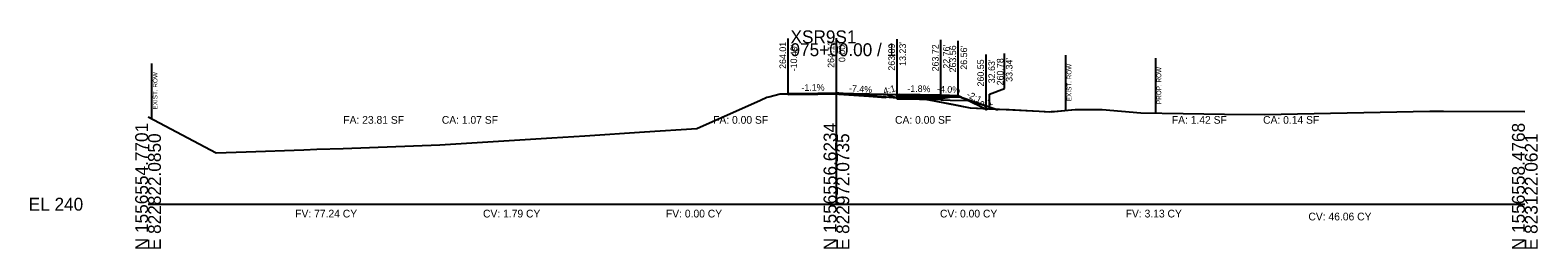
# Model space of a CAD drawing. Extents: x -26 to 823017, y -16 to 1558356.
# Drawn here: x 1974.3 to 2302.8, y 5990.3 to 6037.8 of the extents above; entities that cross this region are included whole.
import ezdxf

# ---------------------------------------------------------------- set-up
doc = ezdxf.new("R2010")
doc.units = 0
for name, color, linetype in [('ASPHALT_19MM1', 7, 'Continuous'), ('CONST_DCH', 7, 'Continuous'), ('CONST_LV3', 7, 'Continuous'), ('Draft_XS_Grid', 7, 'Continuous'), ('DTM_CORRIDOR', 7, 'Continuous'), ('DTM_P_FINISHED_GRADE2', 7, 'Continuous'), ('DTM_X_GROUND', 7, 'Continuous'), ('SLOPE_STAKES_FILL', 7, 'Continuous'), ('X_TRANS_EOP', 7, 'Continuous'), ('XS_CELL', 7, 'Continuous'), ('XS_P_ASPHALT', 7, 'Continuous'), ('XS_P_DR_GRAVEL', 7, 'Continuous'), ('XS_P_GROUND', 7, 'Continuous'), ('XS_P_NULL_POINT', 7, 'Continuous'), ('XS_P_ROW', 7, 'Continuous'), ('XS_P_SHOULDER', 7, 'Continuous'), ('XS_P_SUBGRADE_GRANULAR', 7, 'Continuous'), ('XS_P_SUBGRADE_LEVELING', 7, 'Continuous'), ('XS_P_SUBGRADE_MILLING', 7, 'Continuous'), ('XS_P_SUBGRADE_UNDERCUT', 7, 'Continuous'), ('XS_P_TX_CLEARZONE', 7, 'Continuous'), ('XS_P_TX_FS_BS', 7, 'Continuous'), ('XS_SHEET_EW_TX_AREA', 7, 'Continuous'), ('XS_SHEET_EW_TX_VOLUME', 7, 'Continuous'), ('XS_X_ROW', 7, 'Continuous')]:
    doc.layers.add(name, color=color, linetype=linetype)

msp = doc.modelspace()

# ---------------------------------------------------------------- linework, layer by layer
at = {"layer": 'ASPHALT_19MM1'}
msp.add_lwpolyline([(2163.23, 6023.72), (2163.23, 6023.51), (2172.76, 6023.34), (2172.76, 6023.55), (2163.23, 6023.72)], dxfattribs=at)
at = {"layer": 'CONST_LV3'}
for points in [[(2000, 6019.04), (2014.82, 6011.15), (2021.41, 6011.39), (2033.95, 6011.84), (2036.76, 6011.94), (2042.5, 6012.14), (2063.56, 6012.92), (2088.01, 6014.41), (2095.16, 6014.88), (2108.14, 6015.72), (2119.6, 6016.47), (2133.42, 6022.63), (2134.82, 6023.26), (2135.28, 6023.37), (2137.74, 6023.99), (2139.51, 6024.01), (2139.51, 6024.01)], [(2150, 6024.12), (2164, 6023.84)], [(2160.76, 6023.33), (2160.76, 6023.33), (2163.2, 6023.14), (2163.2, 6023.14), (2163.2, 6023.14), (2163.2, 6023.14), (2163.2, 6023.14), (2163.2, 6023.14), (2163.23, 6023.14), (2163.48, 6023.13), (2172.76, 6022.97), (2176.07, 6023.49), (2176.56, 6023.56), (2177.39, 6023.15), (2185.06, 6020.55), (2185.12, 6020.57), (2185.42, 6020.67), (2185.45, 6020.68), (2185.55, 6020.67), (2187.62, 6020.57), (2194.18, 6020.23), (2196.34, 6020.12), (2196.78, 6020.13), (2197.32, 6020.15), (2201.99, 6020.6), (2202.01, 6020.6), (2203.42, 6020.59), (2203.8, 6020.59), (2203.91, 6020.59), (2204.23, 6020.59), (2205.44, 6020.59), (2205.51, 6020.59), (2207.9, 6020.6), (2216.3, 6019.84), (2225.55, 6019.71), (2234.55, 6019.59), (2243.31, 6019.48), (2279.32, 6020.24), (2282.28, 6020.24), (2300, 6020.14)], [(2162.76, 6023.89), (2162.76, 6023.89), (2164, 6023.84)]]:
    msp.add_lwpolyline(points, dxfattribs=at)
at = {"layer": 'DTM_P_FINISHED_GRADE2'}
msp.add_lwpolyline([(2139.51, 6024.01), (2150, 6024.12), (2160.76, 6023.93)], dxfattribs=at)
at = {"layer": 'DTM_X_GROUND'}
for points in [[(2000, 6019.04), (2014.82, 6011.15), (2021.41, 6011.39), (2033.95, 6011.84), (2036.76, 6011.94), (2042.5, 6012.14), (2063.56, 6012.92), (2088.01, 6014.41), (2095.16, 6014.88), (2108.14, 6015.72), (2119.6, 6016.47), (2133.42, 6022.63), (2134.82, 6023.26), (2135.28, 6023.37), (2137.74, 6023.99), (2145.94, 6024.08), (2150.52, 6024.13), (2157.03, 6024.01), (2163.23, 6023.89), (2164.44, 6023.59), (2164.57, 6023.58), (2164.58, 6023.58), (2165.92, 6023.55), (2168.57, 6023.01), (2170.49, 6022.66), (2171.28, 6022.48), (2179.17, 6020.98), (2185.55, 6020.65), (2194.18, 6020.21), (2196.78, 6020.1), (2201.99, 6020.6), (2203.42, 6020.59), (2207.9, 6020.6), (2216.3, 6019.84), (2225.55, 6019.71), (2234.55, 6019.59), (2243.31, 6019.48), (2279.32, 6020.24), (2282.28, 6020.24), (2300, 6020.14)], [(2000, 6019.04), (2014.82, 6011.15), (2021.41, 6011.39), (2033.95, 6011.84), (2036.76, 6011.94), (2042.5, 6012.14), (2063.56, 6012.92), (2088.01, 6014.41), (2095.16, 6014.88), (2108.14, 6015.72), (2119.6, 6016.47), (2133.42, 6022.63), (2134.82, 6023.26), (2135.28, 6023.37), (2137.74, 6023.99), (2145.94, 6024.08), (2150.52, 6024.13), (2157.03, 6023.62), (2163.2, 6023.14), (2163.2, 6023.14), (2163.2, 6023.14), (2163.2, 6023.14), (2163.2, 6023.14), (2163.2, 6023.14), (2163.23, 6023.14), (2163.48, 6023.13), (2172.76, 6022.97), (2176.07, 6023.49), (2176.56, 6023.56), (2177.39, 6023.15), (2185.06, 6020.55), (2185.12, 6020.57), (2185.42, 6020.67), (2185.45, 6020.68), (2185.55, 6020.67), (2187.62, 6020.57), (2194.18, 6020.23), (2196.34, 6020.12), (2196.78, 6020.13), (2197.32, 6020.15), (2201.99, 6020.6), (2202.01, 6020.6), (2203.42, 6020.59), (2203.8, 6020.59), (2203.91, 6020.59), (2204.23, 6020.59), (2205.44, 6020.59), (2205.51, 6020.59), (2207.9, 6020.6), (2216.3, 6019.84), (2225.55, 6019.71), (2234.55, 6019.59), (2243.31, 6019.48), (2279.32, 6020.24), (2282.28, 6020.24), (2300, 6020.14)], [(2000, 6019.04), (2014.82, 6011.15), (2021.41, 6011.39), (2033.95, 6011.84), (2036.76, 6011.94), (2042.5, 6012.14), (2063.56, 6012.92), (2088.01, 6014.41), (2095.16, 6014.88), (2108.14, 6015.72), (2119.6, 6016.47), (2133.42, 6022.63), (2134.82, 6023.26), (2135.28, 6023.37), (2137.74, 6023.99), (2139.51, 6024.01), (2139.51, 6024.01), (2150, 6024.12), (2150, 6024.12), (2150, 6024.12), (2150, 6024.12), (2150, 6024.12), (2150, 6024.12), (2150, 6024.12), (2150, 6024.12), (2160.76, 6023.93), (2160.76, 6023.93), (2160.76, 6023.93), (2163.2, 6023.14), (2163.2, 6023.14), (2163.2, 6023.14), (2163.2, 6023.14), (2163.2, 6023.14), (2163.2, 6023.14), (2163.23, 6023.14), (2163.48, 6023.13), (2172.76, 6022.97), (2176.07, 6023.49), (2176.56, 6023.56), (2177.39, 6023.15), (2185.06, 6020.55), (2185.12, 6020.57), (2185.42, 6020.67), (2185.45, 6020.68), (2185.55, 6020.67), (2187.62, 6020.57), (2194.18, 6020.23), (2196.34, 6020.12), (2196.78, 6020.13), (2197.32, 6020.15), (2201.99, 6020.6), (2202.01, 6020.6), (2203.42, 6020.59), (2203.8, 6020.59), (2203.91, 6020.59), (2204.23, 6020.59), (2205.44, 6020.59), (2205.51, 6020.59), (2207.9, 6020.6), (2216.3, 6019.84), (2225.55, 6019.71), (2234.55, 6019.59), (2243.31, 6019.48), (2279.32, 6020.24), (2282.28, 6020.24), (2300, 6020.14)]]:
    msp.add_lwpolyline(points, dxfattribs=at)
at = {"layer": 'X_TRANS_EOP'}
msp.add_lwpolyline([(2163.23, 6023.89), (2163.23, 6023.72), (2172.76, 6023.55), (2172.76, 6023.72), (2163.23, 6023.89)], dxfattribs=at)
at = {"layer": 'XS_CELL'}
for p, q in [((2150, 6000), (2150, 6035)), ((2000, 6000), (2150, 6000)), ((2150, 6000), (2300, 6000))]:
    msp.add_line(p, q, dxfattribs=at)
at = {"layer": 'XS_P_ASPHALT'}
msp.add_lwpolyline([(2139.51, 6024.01), (2150, 6024.12), (2150, 6024.12), (2150, 6024.12), (2160.76, 6023.33), (2160.76, 6023.21), (2150, 6024), (2150, 6024), (2150, 6024), (2139.51, 6023.88), (2139.51, 6024.01)], dxfattribs=at)
at = {"layer": 'XS_P_DR_GRAVEL'}
msp.add_lwpolyline([(2172.76, 6023.72), (2172.76, 6023.34), (2177.17, 6023.26), (2176.56, 6023.56), (2172.76, 6023.72)], dxfattribs=at)
at = {"layer": 'XS_P_GROUND'}
msp.add_lwpolyline([(2183.34, 6020.78), (2182.63, 6020.55), (2181.59, 6021.07), (2176.56, 6023.56)], dxfattribs=at)
at = {"layer": 'XS_P_ROW'}
msp.add_line((2219.57, 6019.79), (2219.57, 6031.79), dxfattribs=at)
at = {"layer": 'XS_P_SHOULDER'}
msp.add_lwpolyline([(2172.76, 6023.72), (2176.56, 6023.56)], dxfattribs=at)
at = {"layer": 'XS_P_SUBGRADE_GRANULAR'}
for points in [[(2163.23, 6022.85), (2163.23, 6023.89)], [(2172.76, 6022.67), (2163.48, 6022.84), (2163.23, 6022.85)], [(2172.76, 6022.67), (2174.77, 6022.64), (2178.59, 6022.55)]]:
    msp.add_lwpolyline(points, dxfattribs=at)
at = {"layer": 'XS_P_SUBGRADE_LEVELING'}
msp.add_lwpolyline([(2160.76, 6023.21), (2160.76, 6023.21), (2157.03, 6023.48), (2157.03, 6023.48), (2150.52, 6023.96), (2150.52, 6023.96), (2150, 6024), (2150, 6024), (2145.94, 6023.95), (2145.94, 6023.95), (2139.51, 6023.88), (2139.51, 6023.88)], dxfattribs=at)
msp.add_lwpolyline([(2160.76, 6023.21), (2160.76, 6023.21), (2157.03, 6023.48), (2157.03, 6023.48), (2150.52, 6023.96), (2150.52, 6023.96), (2150, 6024), (2150, 6024), (2145.94, 6023.95), (2145.94, 6023.95), (2139.51, 6023.88), (2139.51, 6023.88)], dxfattribs=at)
at = {"layer": 'XS_P_SUBGRADE_MILLING'}
msp.add_lwpolyline([(2160.76, 6023.33), (2157.03, 6023.62), (2157.03, 6023.62), (2150.52, 6024.13), (2150.52, 6024.13), (2150, 6024.12), (2150, 6024.12), (2145.94, 6024.08), (2145.94, 6024.08), (2139.51, 6024.01), (2139.51, 6024.01), (2139.51, 6023.88), (2139.51, 6023.88), (2145.94, 6023.95), (2145.94, 6023.95), (2150, 6024), (2150, 6024), (2150.52, 6023.96), (2150.52, 6023.96), (2157.03, 6023.48), (2157.03, 6023.48), (2160.76, 6023.21), (2160.76, 6023.21), (2160.76, 6023.33), (2160.76, 6023.33)], dxfattribs=at)
at = {"layer": 'XS_P_SUBGRADE_UNDERCUT'}
msp.add_lwpolyline([(2163.76, 6023.88), (2165.92, 6023.55), (2171.28, 6022.48), (2175.23, 6021.73), (2179.17, 6020.98), (2184.6, 6020.7), (2177.39, 6023.15), (2176.56, 6023.56), (2176.07, 6023.58), (2172.76, 6023.72)], close=True, dxfattribs=at)
at = {"layer": 'XS_P_TX_CLEARZONE'}
for p, q in [((2139.51, 6024.01), (2139.51, 6036.01)), ((2150, 6024.12), (2150, 6036.12)), ((2163.23, 6023.89), (2163.23, 6035.89)), ((2172.76, 6023.72), (2172.76, 6035.72)), ((2176.56, 6023.56), (2176.56, 6035.56)), ((2182.63, 6020.55), (2182.63, 6032.55)), ((2186.59, 6025.19), (2186.59, 6032.78)), ((2183.34, 6023.94), (2186.59, 6025.19)), ((2183.34, 6020.78), (2183.34, 6023.94))]:
    msp.add_line(p, q, dxfattribs=at)
at = {"layer": 'XS_X_ROW'}
for p, q in [((2200, 6020.41), (2200, 6032.41)), ((2000.84, 6018.6), (2000.84, 6030.6))]:
    msp.add_line(p, q, dxfattribs=at)

# ---------------------------------------------------------------- texts
at = {"layer": 'CONST_DCH'}
for p in [(2139.43, 6023.89), (2149.92, 6024), (2160.68, 6023.21)]:
    msp.add_text('X', height=0.24, dxfattribs=at).set_placement(p)
at = {"layer": 'CONST_LV3'}
msp.add_text('X', height=0.24, dxfattribs=at).set_placement((2162.68, 6023.77))
at = {"layer": 'Draft_XS_Grid'}
msp.add_text('-', height=0.0001, dxfattribs=at).set_placement((2000, 6000))
at = {"layer": 'DTM_CORRIDOR'}
for p in [(2163.15, 6023.77), (2172.68, 6023.6)]:
    msp.add_text('X', height=0.24, dxfattribs=at).set_placement(p)
at = {"layer": 'SLOPE_STAKES_FILL'}
msp.add_text('X', height=0.24, dxfattribs=at).set_placement((2182.55, 6020.43))
at = {"layer": 'XS_CELL'}
for s, p in [('XSR9S1', (2140, 6035)), ('975+00.00 / 1', (2140, 6032.2)), ('EL 240', (1974, 5998.6))]:
    msp.add_text(s, height=2.8, dxfattribs=at).set_placement(p)
for s, p in [('N 1556554.7701', (2000, 5990)), ('N 1556556.6234', (2150, 5990)), ('N 1556558.4768', (2300, 5990)), ('E 822822.0850', (2002.8, 5990)), ('E 822972.0735', (2152.8, 5990)), ('E 823122.0621', (2302.8, 5990))]:
    msp.add_text(s, height=2.8, rotation=90, dxfattribs=at).set_placement(p)
at = {"layer": 'XS_P_NULL_POINT'}
msp.add_text('X', height=0.24, dxfattribs=at).set_placement((2183.26, 6020.66))
at = {"layer": 'XS_P_ROW'}
msp.add_text('PROP. ROW', height=1, rotation=90, dxfattribs=at).set_placement((2220.77, 6021.79))
at = {"layer": 'XS_P_SHOULDER'}
msp.add_text('X', height=0.24, dxfattribs=at).set_placement((2176.48, 6023.44))
at = {"layer": 'XS_P_TX_CLEARZONE'}
for s, p in [('264.01', (2139.03, 6029.43)), ('264.12', (2149.52, 6029.66)), ("13.23'", (2165.15, 6030.09)), ("-10.49'", (2141.43, 6028.91)), ("0.00'", (2151.92, 6030.91)), ('263.89', (2162.75, 6029.05)), ('263.72', (2172.28, 6028.89)), ("22.76'", (2174.68, 6029.48)), ('263.56', (2176.08, 6028.66)), ("26.56'", (2178.48, 6029.26)), ('260.55', (2182.15, 6025.61)), ("32.63'", (2184.55, 6026.31)), ('260.78', (2186.4, 6025.85)), ("33.34'", (2188.36, 6026.62))]:
    msp.add_text(s, height=1.44, rotation=90, dxfattribs=at).set_placement(p)
at = {"layer": 'XS_P_TX_FS_BS'}
for s, rotation, p in [('-1.1%', 0.6371, (2142.38, 6024.64)), ('-7.4%', 355.7859, (2152.7, 6024.53)), ('4:1', 15.7122, (2160.42, 6023.86)), ('-1.8%', 358.9679, (2165.45, 6024.45)), ('-4.0%', 357.7059, (2171.89, 6024.35)), ('-2:1', 333.5857, (2178.23, 6023.4)), ('3:1', 18.2351, (2181.63, 6020.85))]:
    msp.add_text(s, height=1.44, rotation=rotation, dxfattribs=at).set_placement(p)
at = {"layer": 'XS_SHEET_EW_TX_AREA'}
for s, p in [('FA: 23.81 SF', (2042.54, 6017.5)), ('CA: 1.07 SF', (2064.01, 6017.5)), ('FA: 0.00 SF', (2123.13, 6017.5)), ('CA: 0.00 SF', (2162.77, 6017.5)), ('FA: 1.42 SF', (2223.08, 6017.5)), ('CA: 0.14 SF', (2242.97, 6017.5))]:
    msp.add_text(s, height=1.68, dxfattribs=at).set_placement(p)
at = {"layer": 'XS_SHEET_EW_TX_VOLUME'}
for s, p in [('FV: 77.24 CY', (2032.07, 5997.12)), ('CV: 1.79 CY', (2072.99, 5997.12)), ('FV: 0.00 CY', (2112.85, 5997.12)), ('CV: 0.00 CY', (2172.56, 5997.12)), ('FV: 3.13 CY', (2213.03, 5997.12)), ('CV: 46.06 CY', (2252.85, 5996.48))]:
    msp.add_text(s, height=1.68, dxfattribs=at).set_placement(p)
at = {"layer": 'XS_X_ROW'}
for p in [(2201.2, 6022.41), (2002.04, 6020.6)]:
    msp.add_text('EXIST. ROW', height=1, rotation=90, dxfattribs=at).set_placement(p)

doc.saveas('drawing.dxf')
